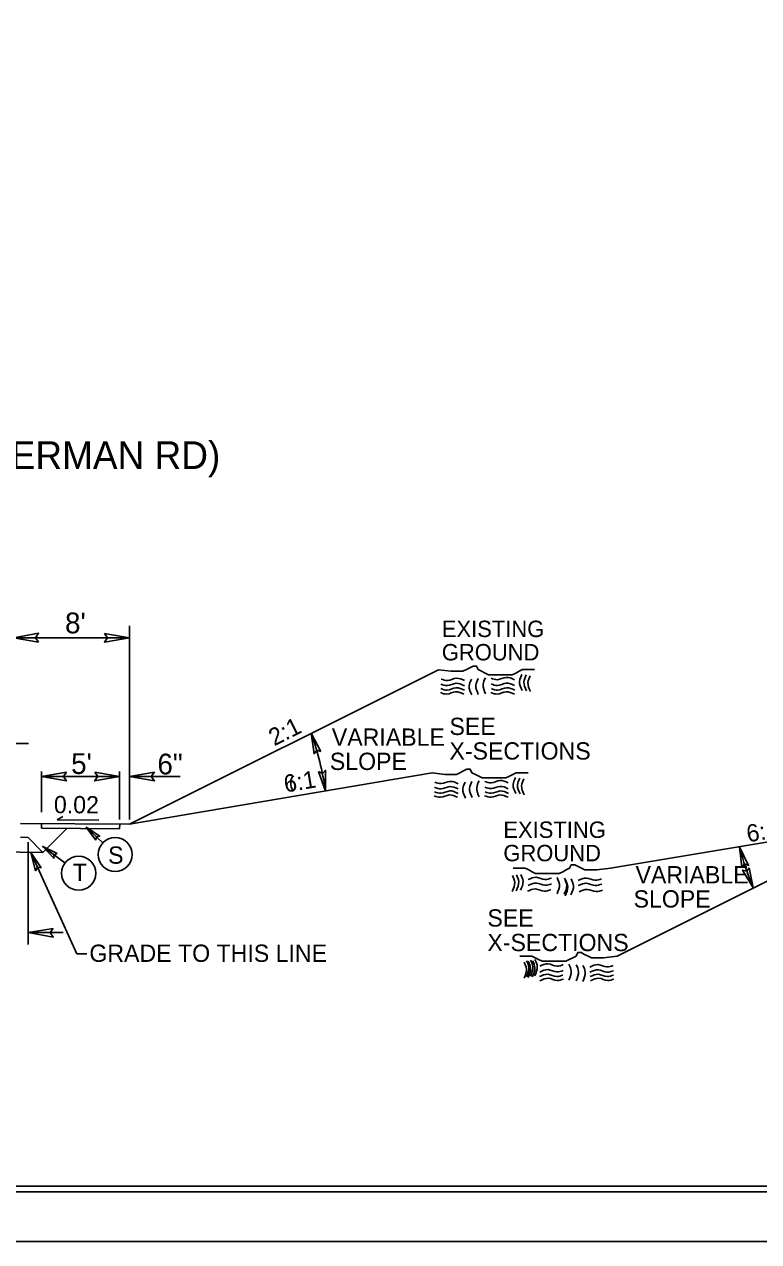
# Model space of a CAD drawing. Extents: x 2294370 to 2294957, y 719276 to 719941.
# Drawn here: x 2294604.5 to 2294670.8, y 719276.3 to 719386.3 of the extents above; entities that cross this region are included whole.
import ezdxf

# ---------------------------------------------------------------- set-up
doc = ezdxf.new("R2010")
doc.units = 0
for name, color, linetype in [('Old_Level_1', 7, 'Continuous'), ('Old_Level_11', 7, 'Continuous'), ('Old_Level_2', 7, 'Continuous'), ('Old_Level_3', 7, 'Continuous'), ('Sheet Cutting Line CELL', 7, 'Continuous'), ('Sheet Plot Border Inside CELL', 7, 'Continuous'), ('Sheet Plot Border Outside CELL', 7, 'Continuous'), ('Sheet Typical CELL', 7, 'Continuous'), ('Typical Hinge Slope Arterial CELL', 7, 'Continuous'), ('Typical ID Circle CELL', 7, 'Continuous'), ('Typical Terminator CELL', 7, 'Continuous'), ('Typical Text ID Circle CELL', 7, 'Continuous')]:
    doc.layers.add(name, color=color, linetype=linetype)

msp = doc.modelspace()

# ---------------------------------------------------------------- linework, layer by layer
at = {"layer": 'Old_Level_1'}
for p, q in [((2294613.96, 719314.05), (2294604.11, 719314.11)), ((2294606.01, 719313.7), (2294606.01, 719314.1)), ((2294613.07, 719313.65), (2294606.01, 719313.7)), ((2294606.12, 719311.49), (2294608.31, 719313.68)), ((2294613.07, 719313.65), (2294613.08, 719314.05)), ((2294604.81, 719312.87), (2294604.11, 719312.88)), ((2294606.12, 719311.49), (2294604.81, 719312.87)), ((2294598.26, 719311.65), (2294606.12, 719311.49))]:
    msp.add_line(p, q, dxfattribs=at)
at = {"layer": 'Old_Level_11'}
for p, q in [((2294613.96, 719318.81), (2294613.96, 719331.99)), ((2294613.96, 719330.91), (2294601.01, 719330.91)), ((2294604.84, 719321.34), (2294601.01, 719321.34)), ((2294606.01, 719315.16), (2294606.01, 719318.81)), ((2294613.07, 719314.5), (2294613.07, 719318.81)), ((2294613.96, 719314.5), (2294613.96, 719318.81)), ((2294613.07, 719318.37), (2294606.01, 719318.37)), ((2294618.54, 719318.37), (2294613.96, 719318.37)), ((2294604.81, 719312.43), (2294604.81, 719303.18)), ((2294609.2, 719302.36), (2294605.05, 719311.49)), ((2294607.97, 719304.26), (2294604.81, 719304.26)), ((2294610.12, 719302.36), (2294609.2, 719302.36))]:
    msp.add_line(p, q, dxfattribs=at)
for points in [[(2294605.74, 719330.52), (2294603.49, 719330.91), (2294605.75, 719331.31), (2294605.46, 719330.91)], [(2294611.71, 719331.3), (2294613.96, 719330.91), (2294611.69, 719330.51), (2294611.98, 719330.91)], [(2294631.25, 719320.62), (2294630.39, 719322.28), (2294630.64, 719320.42), (2294630.88, 719320.74)], [(2294608.26, 719318.75), (2294606.01, 719318.37), (2294608.27, 719317.97), (2294607.99, 719318.37)], [(2294610.82, 719318.75), (2294613.07, 719318.37), (2294610.81, 719317.97), (2294611.1, 719318.37)], [(2294616.21, 719318.75), (2294613.96, 719318.37), (2294616.22, 719317.97), (2294615.93, 719318.37)], [(2294631.06, 719318.82), (2294631.69, 719317.06), (2294631.69, 719318.94), (2294631.41, 719318.65)], [(2294669.3, 719310.17), (2294669.09, 719312.02), (2294669.92, 719310.34), (2294669.54, 719310.47)], [(2294605.99, 719310.11), (2294605.05, 719311.49), (2294605.47, 719309.86), (2294605.65, 719310.17)], [(2294669.97, 719310.13), (2294670.33, 719308.3), (2294669.37, 719309.91), (2294669.76, 719309.81)], [(2294607.06, 719304.65), (2294604.81, 719304.26), (2294607.07, 719303.86), (2294606.79, 719304.26)]]:
    msp.add_lwpolyline(points, close=True, dxfattribs=at)
at = {"layer": 'Old_Level_2'}
for q in [(2294607.94, 719314.75), (2294611.2, 719314.43)]:
    msp.add_line((2294607.42, 719314.46), q, dxfattribs=at)
for points in [[(2294649.43, 719327.6), (2294649.21, 719326.97), (2294649.44, 719326.15)], [(2294649.43, 719327.6), (2294649.21, 719326.97), (2294649.44, 719326.15)], [(2294649.82, 719327.55), (2294649.61, 719326.93), (2294649.84, 719326.11)], [(2294649.82, 719327.55), (2294649.61, 719326.93), (2294649.84, 719326.11)], [(2294650.18, 719327.48), (2294649.97, 719326.86), (2294650.2, 719326.04)], [(2294650.18, 719327.48), (2294649.97, 719326.86), (2294650.2, 719326.04)], [(2294644.23, 719326.57), (2294643.48, 719326.79), (2294642.68, 719326.58), (2294642.11, 719326.71)], [(2294644.23, 719326.57), (2294643.48, 719326.79), (2294642.68, 719326.58), (2294642.11, 719326.71)], [(2294644.23, 719326.17), (2294643.48, 719326.39), (2294642.68, 719326.18), (2294642.11, 719326.31)], [(2294644.23, 719326.17), (2294643.48, 719326.39), (2294642.68, 719326.18), (2294642.11, 719326.31)], [(2294644.25, 719327.04), (2294643.5, 719327.25), (2294642.7, 719327.05), (2294642.13, 719327.18)], [(2294644.25, 719327.04), (2294643.5, 719327.25), (2294642.7, 719327.05), (2294642.13, 719327.18)], [(2294644.87, 719327.18), (2294644.66, 719326.56), (2294644.89, 719325.74)], [(2294644.87, 719327.18), (2294644.66, 719326.56), (2294644.89, 719325.74)], [(2294645.48, 719327.24), (2294645.27, 719326.62), (2294645.49, 719325.79)], [(2294645.48, 719327.24), (2294645.27, 719326.62), (2294645.49, 719325.79)], [(2294646.13, 719327.29), (2294645.92, 719326.67), (2294646.15, 719325.84)], [(2294648.76, 719327.11), (2294648.01, 719327.33), (2294647.21, 719327.12), (2294646.64, 719327.25)], [(2294648.76, 719327.11), (2294648.01, 719327.33), (2294647.21, 719327.12), (2294646.64, 719327.25)], [(2294648.77, 719326.59), (2294648.01, 719326.8), (2294647.22, 719326.6), (2294646.65, 719326.73)], [(2294648.77, 719326.59), (2294648.01, 719326.8), (2294647.22, 719326.6), (2294646.65, 719326.73)], [(2294648.79, 719326.17), (2294648.04, 719326.39), (2294647.24, 719326.18), (2294646.67, 719326.31)], [(2294648.79, 719326.17), (2294648.04, 719326.39), (2294647.24, 719326.18), (2294646.67, 719326.31)], [(2294644.19, 719325.81), (2294643.44, 719326.02), (2294642.64, 719325.82), (2294642.07, 719325.95)], [(2294648.75, 719325.81), (2294648, 719326.02), (2294647.2, 719325.82), (2294646.63, 719325.95)], [(2294628.73, 719318.46), (2294628.53, 719317.84), (2294628.75, 719317.02)], [(2294643.68, 719317.72), (2294642.92, 719317.93), (2294642.13, 719317.73), (2294641.56, 719317.86)], [(2294643.68, 719317.72), (2294642.92, 719317.93), (2294642.13, 719317.73), (2294641.56, 719317.86)], [(2294644.3, 719317.86), (2294644.09, 719317.24), (2294644.32, 719316.42)], [(2294644.3, 719317.86), (2294644.09, 719317.24), (2294644.32, 719316.42)], [(2294644.91, 719317.92), (2294644.69, 719317.3), (2294644.92, 719316.47)], [(2294644.91, 719317.92), (2294644.69, 719317.3), (2294644.92, 719316.47)], [(2294645.56, 719317.97), (2294645.35, 719317.35), (2294645.58, 719316.52)], [(2294645.56, 719317.97), (2294645.35, 719317.35), (2294645.58, 719316.52)], [(2294648.19, 719317.79), (2294647.44, 719318.01), (2294646.64, 719317.8), (2294646.07, 719317.93)], [(2294648.19, 719317.79), (2294647.44, 719318.01), (2294646.64, 719317.8), (2294646.07, 719317.93)], [(2294648.19, 719317.27), (2294647.44, 719317.48), (2294646.65, 719317.28), (2294646.08, 719317.41)], [(2294648.19, 719317.27), (2294647.44, 719317.48), (2294646.65, 719317.28), (2294646.08, 719317.41)], [(2294648.85, 719318.27), (2294648.64, 719317.65), (2294648.87, 719316.83)], [(2294648.85, 719318.27), (2294648.64, 719317.65), (2294648.87, 719316.83)], [(2294649.24, 719318.23), (2294649.03, 719317.61), (2294649.26, 719316.79)], [(2294649.24, 719318.23), (2294649.03, 719317.61), (2294649.26, 719316.79)], [(2294649.61, 719318.16), (2294649.4, 719317.54), (2294649.63, 719316.72)], [(2294649.61, 719318.16), (2294649.4, 719317.54), (2294649.63, 719316.72)], [(2294643.62, 719316.49), (2294642.86, 719316.7), (2294642.07, 719316.5), (2294641.49, 719316.63)], [(2294643.66, 719317.25), (2294642.9, 719317.46), (2294642.11, 719317.26), (2294641.54, 719317.39)], [(2294643.66, 719317.25), (2294642.9, 719317.46), (2294642.11, 719317.26), (2294641.54, 719317.39)], [(2294643.66, 719316.85), (2294642.9, 719317.07), (2294642.11, 719316.86), (2294641.54, 719316.99)], [(2294643.66, 719316.85), (2294642.9, 719317.07), (2294642.11, 719316.86), (2294641.54, 719316.99)], [(2294648.18, 719316.49), (2294647.43, 719316.7), (2294646.63, 719316.5), (2294646.06, 719316.63)], [(2294648.22, 719316.85), (2294647.47, 719317.07), (2294646.67, 719316.86), (2294646.1, 719316.99)], [(2294648.22, 719316.85), (2294647.47, 719317.07), (2294646.67, 719316.86), (2294646.1, 719316.99)], [(2294648.57, 719309.42), (2294648.78, 719308.8), (2294648.55, 719307.98)], [(2294648.57, 719309.42), (2294648.78, 719308.8), (2294648.55, 719307.98)], [(2294648.93, 719309.49), (2294649.14, 719308.87), (2294648.91, 719308.05)], [(2294648.93, 719309.49), (2294649.14, 719308.87), (2294648.91, 719308.05)], [(2294649.32, 719309.53), (2294649.53, 719308.91), (2294649.3, 719308.09)], [(2294649.32, 719309.53), (2294649.53, 719308.91), (2294649.3, 719308.09)], [(2294649.98, 719309.05), (2294650.73, 719309.26), (2294651.53, 719309.06), (2294652.1, 719309.19)], [(2294649.98, 719309.05), (2294650.73, 719309.26), (2294651.53, 719309.06), (2294652.1, 719309.19)], [(2294649.98, 719308.53), (2294650.73, 719308.74), (2294651.52, 719308.54), (2294652.1, 719308.66)], [(2294649.98, 719308.53), (2294650.73, 719308.74), (2294651.52, 719308.54), (2294652.1, 719308.66)], [(2294652.61, 719309.23), (2294652.82, 719308.61), (2294652.6, 719307.78)], [(2294652.61, 719309.23), (2294652.82, 719308.61), (2294652.6, 719307.78)], [(2294653.27, 719309.18), (2294653.48, 719308.55), (2294653.25, 719307.73)], [(2294653.27, 719309.18), (2294653.48, 719308.55), (2294653.25, 719307.73)], [(2294653.36, 719309.03), (2294653.57, 719308.41), (2294653.34, 719307.59)], [(2294653.87, 719309.12), (2294654.09, 719308.5), (2294653.86, 719307.68)], [(2294654.5, 719308.98), (2294655.25, 719309.19), (2294656.04, 719308.99), (2294656.62, 719309.12)], [(2294654.5, 719308.98), (2294655.25, 719309.19), (2294656.04, 719308.99), (2294656.62, 719309.12)], [(2294654.52, 719308.51), (2294655.27, 719308.72), (2294656.06, 719308.52), (2294656.64, 719308.65)], [(2294654.52, 719308.51), (2294655.27, 719308.72), (2294656.06, 719308.52), (2294656.64, 719308.65)], [(2294649.92, 719308), (2294650.67, 719308.21), (2294651.47, 719308.01), (2294652.04, 719308.14)], [(2294649.92, 719308), (2294650.67, 719308.21), (2294651.47, 719308.01), (2294652.04, 719308.14)], [(2294654.59, 719307.96), (2294655.34, 719308.17), (2294656.14, 719307.97), (2294656.71, 719308.1)], [(2294654.59, 719307.96), (2294655.34, 719308.17), (2294656.14, 719307.97), (2294656.71, 719308.1)], [(2294649.63, 719301.6), (2294649.84, 719300.98), (2294649.62, 719300.15)], [(2294649.85, 719301.71), (2294650.06, 719301.09), (2294649.83, 719300.26)], [(2294650, 719301.67), (2294650.21, 719301.05), (2294649.98, 719300.22)], [(2294650.21, 719301.78), (2294650.42, 719301.16), (2294650.2, 719300.33)], [(2294650.39, 719301.71), (2294650.6, 719301.09), (2294650.37, 719300.27)], [(2294650.6, 719301.82), (2294650.82, 719301.2), (2294650.59, 719300.37)], [(2294651.05, 719301.23), (2294651.8, 719301.44), (2294652.6, 719301.24), (2294653.17, 719301.37)], [(2294651.05, 719301.23), (2294651.8, 719301.44), (2294652.6, 719301.24), (2294653.17, 719301.37)], [(2294653.68, 719301.4), (2294653.89, 719300.78), (2294653.67, 719299.96)], [(2294653.68, 719301.4), (2294653.89, 719300.78), (2294653.67, 719299.96)], [(2294654.34, 719301.35), (2294654.55, 719300.73), (2294654.32, 719299.91)], [(2294654.34, 719301.35), (2294654.55, 719300.73), (2294654.32, 719299.91)], [(2294654.94, 719301.3), (2294655.15, 719300.68), (2294654.93, 719299.85)], [(2294654.94, 719301.3), (2294655.15, 719300.68), (2294654.93, 719299.85)], [(2294655.56, 719301.15), (2294656.32, 719301.37), (2294657.11, 719301.17), (2294657.68, 719301.29)], [(2294655.56, 719301.15), (2294656.32, 719301.37), (2294657.11, 719301.17), (2294657.68, 719301.29)], [(2294651.02, 719300.29), (2294651.77, 719300.5), (2294652.57, 719300.3), (2294653.14, 719300.43)], [(2294651.02, 719300.29), (2294651.77, 719300.5), (2294652.57, 719300.3), (2294653.14, 719300.43)], [(2294651.05, 719300.7), (2294651.8, 719300.92), (2294652.59, 719300.71), (2294653.16, 719300.84)], [(2294651.05, 719300.7), (2294651.8, 719300.92), (2294652.59, 719300.71), (2294653.16, 719300.84)], [(2294651.06, 719299.92), (2294651.81, 719300.14), (2294652.61, 719299.94), (2294653.18, 719300.07)], [(2294655.58, 719300.68), (2294656.34, 719300.9), (2294657.13, 719300.69), (2294657.7, 719300.82)], [(2294655.58, 719300.68), (2294656.34, 719300.9), (2294657.13, 719300.69), (2294657.7, 719300.82)], [(2294655.59, 719300.29), (2294656.34, 719300.5), (2294657.13, 719300.3), (2294657.71, 719300.43)], [(2294655.59, 719300.29), (2294656.34, 719300.5), (2294657.13, 719300.3), (2294657.71, 719300.43)], [(2294655.63, 719299.92), (2294656.38, 719300.14), (2294657.18, 719299.94), (2294657.75, 719300.07)]]:
    msp.add_spline(points, degree=3, dxfattribs=at)
at = {"layer": 'Sheet Cutting Line CELL'}
msp.add_line((2294455.16, 719276.34), (2294791.96, 719276.34), dxfattribs=at)
at = {"layer": 'Sheet Plot Border Inside CELL'}
msp.add_lwpolyline([(2294791.06, 719491.85), (2294457.76, 719491.85), (2294457.76, 719280.83), (2294791.06, 719280.83)], close=True, dxfattribs=at)
at = {"layer": 'Sheet Plot Border Outside CELL'}
for points in [[(2294455.16, 719276.34), (2294791.96, 719276.34), (2294791.96, 719496.34), (2294455.16, 719496.34)], [(2294791.96, 719496.34), (2294455.16, 719496.34), (2294455.16, 719276.34), (2294791.96, 719276.34)]]:
    msp.add_lwpolyline(points, close=True, dxfattribs=at)
at = {"layer": 'Sheet Typical CELL'}
msp.add_lwpolyline([(2294788.56, 719491.34), (2294488.56, 719491.34), (2294488.56, 719281.34), (2294788.56, 719281.34)], close=True, dxfattribs=at)
at = {"layer": 'Typical Hinge Slope Arterial CELL'}
for p, q in [((2294641.9, 719328.02), (2294613.96, 719314.05)), ((2294641.32, 719318.7), (2294613.96, 719314.05)), ((2294657.43, 719310.08), (2294682.13, 719314.2)), ((2294658.03, 719302.15), (2294682.13, 719314.2))]:
    msp.add_line(p, q, dxfattribs=at)
for points in [[(2294641.9, 719328.02), (2294643.02, 719327.88), (2294643.33, 719327.88), (2294643.79, 719327.88), (2294644.1, 719327.88), (2294644.41, 719328.03), (2294644.71, 719328.19), (2294645.02, 719328.34), (2294645.33, 719328.34), (2294645.48, 719328.03), (2294645.79, 719327.88), (2294646.1, 719327.72), (2294646.41, 719327.57), (2294646.72, 719327.57), (2294647.02, 719327.57), (2294647.33, 719327.57), (2294647.64, 719327.57), (2294647.95, 719327.57), (2294648.26, 719327.57), (2294648.56, 719327.57), (2294648.87, 719327.72), (2294649.18, 719327.88), (2294649.49, 719328.03), (2294649.95, 719328.03), (2294650.26, 719328.03), (2294650.57, 719328.03)], [(2294641.32, 719318.7), (2294642.45, 719318.56), (2294642.75, 719318.56), (2294643.22, 719318.56), (2294643.52, 719318.56), (2294643.83, 719318.71), (2294644.14, 719318.87), (2294644.45, 719319.02), (2294644.76, 719319.02), (2294644.91, 719318.71), (2294645.22, 719318.56), (2294645.53, 719318.4), (2294645.84, 719318.25), (2294646.14, 719318.25), (2294646.45, 719318.25), (2294646.76, 719318.25), (2294647.07, 719318.25), (2294647.38, 719318.25), (2294647.68, 719318.25), (2294647.99, 719318.25), (2294648.3, 719318.4), (2294648.61, 719318.56), (2294648.91, 719318.71), (2294649.38, 719318.71), (2294649.69, 719318.71), (2294649.99, 719318.71)], [(2294657.43, 719310.08), (2294656.2, 719309.93), (2294655.89, 719309.93), (2294655.43, 719309.93), (2294655.12, 719309.93), (2294654.81, 719310.08), (2294654.51, 719310.24), (2294654.2, 719310.39), (2294653.89, 719310.39), (2294653.74, 719310.08), (2294653.43, 719309.93), (2294653.12, 719309.77), (2294652.81, 719309.62), (2294652.5, 719309.62), (2294652.2, 719309.62), (2294651.89, 719309.62), (2294651.58, 719309.62), (2294651.27, 719309.62), (2294650.96, 719309.62), (2294650.66, 719309.62), (2294650.35, 719309.77), (2294650.04, 719309.93), (2294649.73, 719310.08), (2294649.27, 719310.08), (2294648.96, 719310.08), (2294648.65, 719310.08)], [(2294658.03, 719302.15), (2294656.79, 719301.99), (2294656.49, 719301.99), (2294656.02, 719301.99), (2294655.72, 719301.99), (2294655.41, 719302.15), (2294655.1, 719302.3), (2294654.79, 719302.46), (2294654.48, 719302.46), (2294654.33, 719302.15), (2294654.02, 719301.99), (2294653.71, 719301.84), (2294653.41, 719301.68), (2294653.1, 719301.68), (2294652.79, 719301.68), (2294652.48, 719301.68), (2294652.17, 719301.68), (2294651.87, 719301.68), (2294651.56, 719301.68), (2294651.25, 719301.68), (2294650.94, 719301.84), (2294650.63, 719301.99), (2294650.33, 719302.15), (2294649.86, 719302.15), (2294649.56, 719302.15), (2294649.25, 719302.15)]]:
    msp.add_lwpolyline(points, dxfattribs=at)
for centre, start, end in [((2294603.07, 719312.73), 8.6168, 19.2751), ((2294697.11, 719319.27), 194.5, 202.279)]:
    msp.add_arc(centre, 28.94, start, end, dxfattribs=at)
at = {"layer": 'Typical ID Circle CELL'}
for p, q in [((2294611.54, 719312.38), (2294610.05, 719313.78)), ((2294608.13, 719310.56), (2294606.12, 719312.05))]:
    msp.add_line(p, q, dxfattribs=at)
for centre in [(2294612.67, 719311.32), (2294609.37, 719309.63)]:
    msp.add_circle(centre, 1.54, dxfattribs=at)
at = {"layer": 'Typical Terminator CELL'}
for points in [[(2294610.93, 719312.63), (2294610.05, 719313.78), (2294611.27, 719312.99), (2294610.97, 719312.92)], [(2294607.42, 719311.4), (2294606.12, 719312.05), (2294607.13, 719310.99), (2294607.13, 719311.3)]]:
    msp.add_lwpolyline(points, close=True, dxfattribs=at)

# ---------------------------------------------------------------- texts
at = {"layer": 'Old_Level_1'}
for s, height, rotation, p in [('EXISTING', 1.484, 360, (2294642.19, 719330.97)), ('GROUND', 1.484, 360, (2294642.19, 719328.86)), ('2:1', 1.562, 26.5651, (2294627.04, 719321.09)), ('SEE ', 1.562, 360, (2294642.88, 719322.12)), ('X-SECTIONS', 1.562, 360, (2294642.88, 719319.9)), ('6:1', 1.562, 9.4623, (2294628.05, 719316.92)), ('EXISTING', 1.484, 360, (2294647.75, 719312.82)), ('6:1', 1.562, 9.4623, (2294669.86, 719312.42)), ('GROUND', 1.484, 360, (2294647.75, 719310.71)), ('SEE ', 1.562, 360, (2294646.31, 719304.81)), ('X-SECTIONS', 1.562, 360, (2294646.31, 719302.59))]:
    msp.add_text(s, height=height, rotation=rotation, dxfattribs=at).set_placement(p)
at = {"layer": 'Old_Level_11'}
for s, p in [("8'", (2294608.14, 719331.31)), ("5'", (2294608.69, 719318.6)), ('6"', (2294616.49, 719318.56))]:
    msp.add_text(s, height=1.875, dxfattribs=at).set_placement(p)
msp.add_text('GRADE TO THIS LINE', height=1.5625, rotation=360, dxfattribs=at).set_placement((2294610.34, 719301.62))
at = {"layer": 'Old_Level_3'}
for s, height, rotation, p in [('-Y- SR 1160 (MT HERMAN RD)', 2.5, 360, (2294574.62, 719346.16)), ('0.02', 1.562, 359.6305, (2294607.13, 719315.06))]:
    msp.add_text(s, height=height, rotation=rotation, dxfattribs=at).set_placement(p)
at = {"layer": 'Typical Hinge Slope Arterial CELL'}
for s, p in [('VARIABLE ', (2294632.25, 719321.15)), ('SLOPE', (2294632.07, 719318.96)), ('VARIABLE ', (2294659.7, 719308.71)), ('SLOPE', (2294659.52, 719306.53))]:
    msp.add_text(s, height=1.562, dxfattribs=at).set_placement(p)
at = {"layer": 'Typical Text ID Circle CELL'}
for s, p in [('S', (2294612.03, 719310.49)), ('T', (2294608.84, 719308.92))]:
    msp.add_text(s, height=1.56, dxfattribs=at).set_placement(p)

doc.saveas('drawing.dxf')
